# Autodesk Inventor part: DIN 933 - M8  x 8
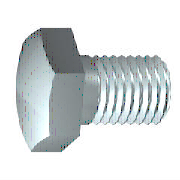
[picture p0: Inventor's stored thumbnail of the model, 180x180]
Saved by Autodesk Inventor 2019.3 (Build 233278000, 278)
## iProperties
Created: 2018-01
Part Number: DIN 933 - M8  x 8
Material: Ocel, měkká
Description: Šestihranný šroub
Document SubType Name: Modeling
Standard: DIN 933
Designer: B-hon
Standards Organization: DIN
Language: cs-CZ
Size Designation: M8  x 8
Categories: <MemberInstance><Categories><Category DisplayName="Spojovací materiál" InternalName="e4da775c-781d-43d5-af7c-5136215cf5a6" Mnemonic="FSTN"><Category DisplayName
Density: 7.85 g/cm^3
Appearance: Pololeštěná
IsCustomPart: 0
Author: B-hon
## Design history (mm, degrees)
sketch "Náčrt1"
  geometry: L1 (0, 5.7)-(0, 3.662); L2 (3.75, 4)-(8, 4); L3 (8, 4)-(8, 0); L4 (8, 0)-(-0.6, 0); L5 (-2.32, 0)-(9.72, 0) reference; L6 (-0.6, 0)-(-0.6, 5.7); L7 (-0.6, 5.7)-(0, 5.7); L8 (3.75, 4)-(2.983, 3.662); L9 (2.983, 3.662)-(0, 3.662); L10 (0, -1.14)-(0, 6.84) reference
  constraints: 16 end point, 2 collinear, 2 perpendicular, 1 parallel
  dimensions: "d0" = 8 distance between parallel lines of L3 L1 (= NLG); "d1" = 4.25 distance from line of L2.start L3 (= GEL); "d2" = 8 diameter of L2 L4 (= GD); "d9" = 0.6001 distance between parallel lines of L6 L1 (computed from SD); "d10" = 11.4 diameter of L7 L4 (= SD2); "d13" = 0.76691 horizontal distance of L2.start L8.end (computed from GAL); "d14" = 7.32342 diameter of L9 L4 (= BDM)
revolve "Těleso" sketch "Náčrt1" stored, may be unused: angle "d12" = 90 deg
sketch "Náčrt2"
  geometry: L1 (0, 7.506)-(6.5, 3.753); L2 (6.5, 3.753)-(6.5, -3.753); L3 (6.5, -3.753)-(0, -7.506); L4 (0, -7.506)-(-6.5, -3.753); L5 (-6.5, -3.753)-(-6.5, 3.753); L6 (-6.5, 3.753)-(0, 7.506); 2 further points
  constraints: 12 end point, 1 coincident, 1 vertical, 11 other
  dimensions: "d11" = 13 distance between parallel lines of L5 L2 (= SW)
extrude "Hlava" join sketch "Náčrt2" distance "d3" = 4.7 (= KOH - SD); taper "d4" = 0 deg
sketch "Náčrt4"
  geometry: L1 (-5.3, 6.5)-(-5.3, 7.506); L2 (-5.3, 7.506)-(-4.72, 7.506); L3 (-4.72, 7.506)-(-5.3, 6.5); L4 (-6.24, 0)-(0.34, 0) reference; L5 (-0.6, 7.506)-(-5.3, 7.506) reference; L6 (-5.3, 3.753)-(-5.3, 7.506) reference
  constraints: 6 end point, 2 collinear, 1 perpendicular, 1 vertical
  dimensions: "d5" = 30 deg angle of L3 L1 (= ANG1); "d19" = 13 diameter of L1.start L4 (= SW0)
revolve "Zkosení1" sketch "Náčrt4" stored, may be unused: angle "d21" = 90 deg
workplane "Work Plane1"
body "Solid1"
feature "Závit" dims "d15" = 4.25 (= GEL), "d16" = 0
chamfer "Zkosení2" distance "d6" = 0.76681 (= -0.5 x SPD + 0.5 x GD); stored, may be unused: second distance "d7" = 0.76691 (computed from GUL), angle "d55" = 45 deg
other parameters: "NLG" = 8 [user parameter; used in 1 equation term], "GD" = 8 (= NND) [user parameter; used in 2 equation terms], "BDM" = 7.32342 [user parameter; used in 1 equation term], "KOH" = 5.3 [user parameter; used in 1 equation term], "GEL" = 4.25 [user parameter; used in 2 equation terms], "SW" = 13 [user parameter; used in 2 equation terms], "SW0" = 13 [user parameter; used in 1 equation term], "SPD" = 6.46637 (= NND - 1.2269 x PTC) [user parameter; used in 1 equation term], "SD2" = 11.4 [user parameter; used in 1 equation term], "SD" = 0.6 [user parameter; used in 2 equation terms], "ANG1" = 30 deg [user parameter; used in 1 equation term], "GAL" = 0.76681 (= 0.61345 x PTC) [user parameter; used in 1 equation term], "GUL" = 0.76681 (= 0.61345 x PTC) [user parameter; used in 1 equation term], "d8" = 0, "RR" = 0.4 [user parameter], "d57" = 0, "d58" = 0, "TPU" = 8 (computed from PTC) [user parameter], "GD1" = 6.46637 (= THREADDIA - 1.2269 x PTC) [user parameter], "THREADDIA" = 8 [user parameter; used in 1 equation term], "TOA" = 30 deg [user parameter], "PTC" = 1.25 [user parameter; used in 5 equation terms], "NND" = 8 [user parameter; used in 2 equation terms], "E0" = 15.015 (= 1.155 x SW) [user parameter]
